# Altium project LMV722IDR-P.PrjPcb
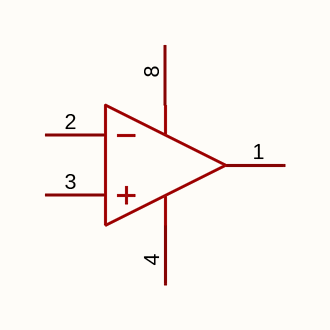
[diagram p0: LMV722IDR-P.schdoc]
1 sheet, 1 parts. Net scope: global (net labels, ports and power ports of the same name join across sheets).

## Sheet LMV722IDR-P.schdoc
size 127 x 101 mm

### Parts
U?  lmv722idr-p  [SOP-8_L4.9-W3.9-P1.27-LS6.0-BL]  (value not drawn)  (part A of 2)

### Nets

Not connected (* = marked no-connect by the designer): U? 1(OUTA) 2(INA-) 3(INA+) 4(-VS) 8(+VS)

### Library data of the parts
U? = lmv722idr-p: 放大器数:2;轨到轨:轨到轨输入,轨到轨输出;增益带宽积(GBW):10MHz;输入失调电压(Vos):5mV;压摆率(SR):4.5V/us;输入偏置电流(Ib):100pA;; Manufacturer: TECH PUBLIC(台舟); AddInBom: yes; ModelId: 75c24a7891ee4dd6bdac16a7163ff87e; ModelName: SOP-8_L4.9-W3.9-P1.27-LS6.0-BL-1; ModelTransform: 192.913,236.22,0,0,0,0,-0.393,2.749,0; Number of Channels: 2; Maximum Power Supply Range (Vdd-Vss): 7V; Gain Bandwidth Product: 10MHz; Vos - Input Offset Voltage: 5mV; Input Offset Voltage Drift(Vos TC): 1.5uV/℃; Ib - Input Bias Current: 100pA; Input Offset Current(Ios): 1pA; Input Voltage Noise Density: 15nV/√Hz@30kHz; Common Mode Rejection Ratio(CMRR): 80dB; Quiescent Current: 800uA; Output Current: 50mA; Single supply: 2.2V~5.5V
